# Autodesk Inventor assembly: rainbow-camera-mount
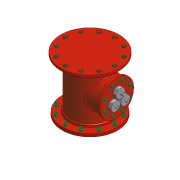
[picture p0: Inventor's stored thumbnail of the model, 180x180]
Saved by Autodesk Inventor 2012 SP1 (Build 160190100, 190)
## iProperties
Created: 2012-03
Part Number: rainbow-camera-mount
Document SubType Name: Assembly
Designer: jdh
Mass: 8726.63 g
Surface Area: 10535.3 cm^2
Volume: 4107.03 cm^3
Density: 2.1248 g/cm^3
Author: jdh
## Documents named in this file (3)
- C:\Documents and Settings\LACO\My Documents\Inventor\rainbow-camera-mount\01 assemblies\rainbow-camera-mount.iam
- C:\Documents and Settings\LACO\My Documents\Inventor\rainbow-camera-mount\01 assemblies\rainbow-camera-shell.iam
- C:\Documents and Settings\LACO\My Documents\Inventor\rainbow-camera-mount\01 assemblies\rainbow-camera-insert.iam
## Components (2 placed, 2 different names)
1. rainbow-camera-shell:1 [sub-assembly] — Mate:1, Insert:1
2. rainbow-camera-insert:1 [sub-assembly] — Mate:1, Insert:1
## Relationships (2: Mate 1, Insert 1)
- Mate:1: rainbow-camera-shell:1 ↔ rainbow-camera-insert:1
- Insert:1: rainbow-camera-shell:1 ↔ rainbow-camera-insert:1
